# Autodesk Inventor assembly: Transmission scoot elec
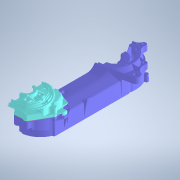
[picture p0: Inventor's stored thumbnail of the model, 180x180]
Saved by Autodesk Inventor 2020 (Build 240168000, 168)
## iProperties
Created: 2004-11
Part Number: Transmission scoot elec
Document SubType Name: Assembly
Designer: Bruno
Author: Bruno
Sending System: SolidWorks 2011
Last Author: Professeur
Last Saved: 2014-11-10
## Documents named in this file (4)
- D:\Téléchargements-2016-17\scoot_elec\Transmission scoot elec.iam
- D:\Téléchargements-2016-17\scoot_elec\Carter gauche.ipt
- D:\Téléchargements-2016-17\scoot_elec\Joint carter.ipt
- D:\Téléchargements-2016-17\scoot_elec\Carter droit.ipt
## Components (3 placed, 3 different names)
1. Carter gauche:1
2. JOINT CARTER:1
3. Carter droit:1
